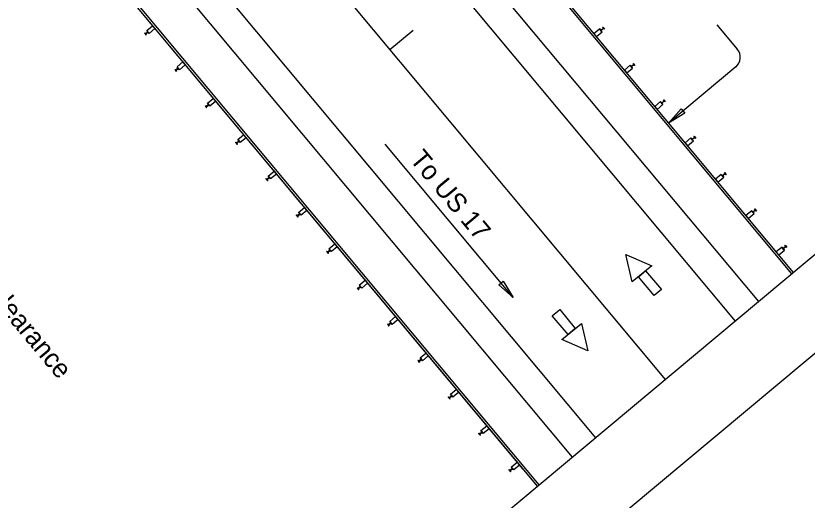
# Model space of a CAD drawing. Extents: x 2042995 to 2043795, y 305365 to 306249.
# Drawn here: x 2043611.9 to 2043716.3, y 305612.5 to 305676.3 of the extents above; entities that cross this region are included whole.
import ezdxf

# ---------------------------------------------------------------- set-up
doc = ezdxf.new("R2010")
doc.units = 0
for name, color, linetype in [('BR_AUTO DIMENSION', 7, 'Continuous'), ('BR_BORDER LINES', 7, 'Continuous'), ('BR_CENTER LINES', 7, 'Continuous'), ('BR_PROPOSED_TRAVELWAY', 7, 'Continuous'), ('BR_STRUCTURAL STEEL', 7, 'Continuous'), ('BR_TABLE LINES', 7, 'Continuous'), ('BR_TEXT', 7, 'Continuous'), ('RD_SHT_IplotShp', 7, 'Continuous')]:
    doc.layers.add(name, color=color, linetype=linetype)

msp = doc.modelspace()

# ---------------------------------------------------------------- linework, layer by layer
at = {"layer": 'BR_AUTO DIMENSION'}
for p, q in [((2043704.39, 305675.16), (2043707.07, 305671.95)), ((2043706.86, 305669.6), (2043698.01, 305662.21)), ((2043677.53, 305639.2), (2043660.64, 305659.42))]:
    msp.add_line(p, q, dxfattribs=at)
for points in [[(2043700.17, 305663.53), (2043698.01, 305662.21), (2043699.69, 305664.1)], [(2043676.21, 305641.35), (2043677.53, 305639.2), (2043675.64, 305640.87)]]:
    msp.add_lwpolyline(points, close=True, dxfattribs=at)
msp.add_arc((2043705.79, 305670.88), 1.67, 309.8684, 39.8684, dxfattribs=at)
at = {"layer": 'BR_BORDER LINES'}
msp.add_line((2043458.12, 305428.42), (2043780.48, 305697.65), dxfattribs=at)
at = {"layer": 'BR_CENTER LINES'}
for p, q in [((2043547.53, 305808.07), (2043697.58, 305628.41)), ((2043661.25, 305671.9), (2043664.32, 305674.46))]:
    msp.add_line(p, q, dxfattribs=at)
at = {"layer": 'BR_PROPOSED_TRAVELWAY'}
for p, q in [((2043592.55, 305788.48), (2043714.46, 305642.51)), ((2043582.48, 305784.94), (2043706.79, 305636.1)), ((2043557.54, 305777.36), (2043688.37, 305620.72)), ((2043564.4, 305753.54), (2043678.77, 305616.61)), ((2043564.46, 305753.47), (2043678.77, 305616.61)), ((2043625.29, 305739.92), (2043709.86, 305638.66)), ((2043608.34, 305710.3), (2043685.3, 305618.15))]:
    msp.add_line(p, q, dxfattribs=at)
at = {"layer": 'BR_STRUCTURAL STEEL'}
for p, q in [((2043611.99, 305764.75), (2043714.24, 305642.32)), ((2043612.21, 305764.94), (2043714.46, 305642.51)), ((2043586.04, 305727.63), (2043680.69, 305614.31)), ((2043586.27, 305727.82), (2043680.92, 305614.49)), ((2043629.27, 305674.37), (2043629.23, 305674.34)), ((2043629.23, 305674.34), (2043629.33, 305674.23)), ((2043629.48, 305674.11), (2043629.27, 305674.37)), ((2043688.97, 305674.55), (2043689, 305674.57)), ((2043689.18, 305674.29), (2043688.97, 305674.55)), ((2043689, 305674.57), (2043689.09, 305674.46)), ((2043689.09, 305674.46), (2043689.41, 305674.73)), ((2043689.44, 305674.7), (2043689.12, 305674.43)), ((2043689.12, 305674.43), (2043689.21, 305674.32)), ((2043689.21, 305674.32), (2043689.18, 305674.29)), ((2043689.32, 305674.84), (2043689.35, 305674.87)), ((2043689.41, 305674.73), (2043689.32, 305674.84)), ((2043689.35, 305674.87), (2043689.57, 305674.61)), ((2043689.53, 305674.58), (2043689.44, 305674.7)), ((2043689.57, 305674.61), (2043689.53, 305674.58)), ((2043628.91, 305674.07), (2043628.88, 305674.05)), ((2043628.88, 305674.05), (2043629.1, 305673.79)), ((2043629.01, 305673.96), (2043628.91, 305674.07)), ((2043629.33, 305674.23), (2043629.01, 305673.96)), ((2043629.03, 305673.93), (2043629.35, 305674.2)), ((2043629.13, 305673.82), (2043629.03, 305673.93)), ((2043629.1, 305673.79), (2043629.13, 305673.82)), ((2043629.35, 305674.2), (2043629.45, 305674.09)), ((2043629.45, 305674.09), (2043629.48, 305674.11)), ((2043693.33, 305670.04), (2043693.36, 305670.07)), ((2043693.36, 305670.07), (2043693.57, 305669.81)), ((2043632.92, 305669.28), (2043632.89, 305669.25)), ((2043632.89, 305669.25), (2043633.1, 305669)), ((2043633.01, 305669.17), (2043632.92, 305669.28)), ((2043633.33, 305669.43), (2043633.01, 305669.17)), ((2043633.04, 305669.13), (2043633.36, 305669.4)), ((2043633.13, 305669.02), (2043633.04, 305669.13)), ((2043633.1, 305669), (2043633.13, 305669.02)), ((2043633.27, 305669.57), (2043633.24, 305669.54)), ((2043633.24, 305669.54), (2043633.33, 305669.43)), ((2043633.49, 305669.32), (2043633.27, 305669.57)), ((2043633.36, 305669.4), (2043633.45, 305669.29)), ((2043633.45, 305669.29), (2043633.49, 305669.32)), ((2043692.97, 305669.75), (2043693.01, 305669.78)), ((2043693.19, 305669.49), (2043692.97, 305669.75)), ((2043693.01, 305669.78), (2043693.1, 305669.66)), ((2043693.1, 305669.66), (2043693.42, 305669.93)), ((2043693.45, 305669.9), (2043693.13, 305669.63)), ((2043693.13, 305669.63), (2043693.22, 305669.52)), ((2043693.22, 305669.52), (2043693.19, 305669.49)), ((2043693.42, 305669.93), (2043693.33, 305670.04)), ((2043693.54, 305669.79), (2043693.45, 305669.9)), ((2043693.57, 305669.81), (2043693.54, 305669.79)), ((2043696.98, 305664.95), (2043697.01, 305664.98)), ((2043697.2, 305664.7), (2043696.98, 305664.95)), ((2043697.01, 305664.98), (2043697.11, 305664.87)), ((2043697.11, 305664.87), (2043697.43, 305665.13)), ((2043697.45, 305665.1), (2043697.13, 305664.84)), ((2043697.33, 305665.25), (2043697.37, 305665.27)), ((2043697.43, 305665.13), (2043697.33, 305665.25)), ((2043697.37, 305665.27), (2043697.58, 305665.02)), ((2043697.55, 305664.99), (2043697.45, 305665.1)), ((2043697.58, 305665.02), (2043697.55, 305664.99)), ((2043636.93, 305664.48), (2043636.89, 305664.45)), ((2043636.89, 305664.45), (2043637.11, 305664.2)), ((2043637.02, 305664.37), (2043636.93, 305664.48)), ((2043637.34, 305664.64), (2043637.02, 305664.37)), ((2043637.05, 305664.34), (2043637.37, 305664.6)), ((2043637.14, 305664.23), (2043637.05, 305664.34)), ((2043637.11, 305664.2), (2043637.14, 305664.23)), ((2043637.28, 305664.77), (2043637.25, 305664.75)), ((2043637.25, 305664.75), (2043637.34, 305664.64)), ((2043637.49, 305664.52), (2043637.28, 305664.77)), ((2043637.37, 305664.6), (2043637.46, 305664.49)), ((2043637.46, 305664.49), (2043637.49, 305664.52)), ((2043697.13, 305664.84), (2043697.23, 305664.72)), ((2043697.23, 305664.72), (2043697.2, 305664.7)), ((2043640.93, 305659.68), (2043640.9, 305659.66)), ((2043640.9, 305659.66), (2043641.11, 305659.4)), ((2043641.03, 305659.57), (2043640.93, 305659.68)), ((2043641.35, 305659.84), (2043641.03, 305659.57)), ((2043641.05, 305659.54), (2043641.37, 305659.81)), ((2043641.28, 305659.98), (2043641.25, 305659.95)), ((2043641.25, 305659.95), (2043641.35, 305659.84)), ((2043641.5, 305659.72), (2043641.28, 305659.98)), ((2043641.37, 305659.81), (2043641.47, 305659.7)), ((2043641.47, 305659.7), (2043641.5, 305659.72)), ((2043700.99, 305660.16), (2043701.02, 305660.18)), ((2043701.2, 305659.9), (2043700.99, 305660.16)), ((2043701.02, 305660.18), (2043701.11, 305660.07)), ((2043701.11, 305660.07), (2043701.43, 305660.34)), ((2043701.46, 305660.31), (2043701.14, 305660.04)), ((2043701.14, 305660.04), (2043701.23, 305659.93)), ((2043701.23, 305659.93), (2043701.2, 305659.9)), ((2043701.34, 305660.45), (2043701.37, 305660.48)), ((2043701.43, 305660.34), (2043701.34, 305660.45)), ((2043701.37, 305660.48), (2043701.59, 305660.22)), ((2043701.55, 305660.19), (2043701.46, 305660.31)), ((2043701.59, 305660.22), (2043701.55, 305660.19)), ((2043641.15, 305659.43), (2043641.05, 305659.54)), ((2043641.11, 305659.4), (2043641.15, 305659.43)), ((2043705.12, 305655.27), (2043705.44, 305655.54)), ((2043705.47, 305655.51), (2043705.15, 305655.24)), ((2043705.35, 305655.65), (2043705.38, 305655.68)), ((2043705.44, 305655.54), (2043705.35, 305655.65)), ((2043705.38, 305655.68), (2043705.59, 305655.42)), ((2043705.56, 305655.4), (2043705.47, 305655.51)), ((2043644.94, 305654.89), (2043644.91, 305654.86)), ((2043644.91, 305654.86), (2043645.12, 305654.6)), ((2043645.03, 305654.77), (2043644.94, 305654.89)), ((2043645.35, 305655.04), (2043645.03, 305654.77)), ((2043645.06, 305654.74), (2043645.38, 305655.01)), ((2043645.15, 305654.63), (2043645.06, 305654.74)), ((2043645.12, 305654.6), (2043645.15, 305654.63)), ((2043645.29, 305655.18), (2043645.26, 305655.15)), ((2043645.26, 305655.15), (2043645.35, 305655.04)), ((2043645.5, 305654.92), (2043645.29, 305655.18)), ((2043645.38, 305655.01), (2043645.47, 305654.9)), ((2043645.47, 305654.9), (2043645.5, 305654.92)), ((2043704.99, 305655.36), (2043705.03, 305655.39)), ((2043705.21, 305655.1), (2043704.99, 305655.36)), ((2043705.03, 305655.39), (2043705.12, 305655.27)), ((2043705.15, 305655.24), (2043705.24, 305655.13)), ((2043705.24, 305655.13), (2043705.21, 305655.1)), ((2043705.59, 305655.42), (2043705.56, 305655.4)), ((2043649.36, 305650.25), (2043649.04, 305649.98)), ((2043649.3, 305650.38), (2043649.27, 305650.36)), ((2043649.27, 305650.36), (2043649.36, 305650.25)), ((2043649.51, 305650.13), (2043649.3, 305650.38)), ((2043709, 305650.56), (2043709.03, 305650.59)), ((2043709.21, 305650.31), (2043709, 305650.56)), ((2043709.03, 305650.59), (2043709.13, 305650.48)), ((2043709.13, 305650.48), (2043709.45, 305650.74)), ((2043709.47, 305650.71), (2043709.15, 305650.44)), ((2043709.15, 305650.44), (2043709.25, 305650.33)), ((2043709.25, 305650.33), (2043709.21, 305650.31)), ((2043709.35, 305650.86), (2043709.38, 305650.88)), ((2043709.45, 305650.74), (2043709.35, 305650.86)), ((2043709.38, 305650.88), (2043709.6, 305650.63)), ((2043709.57, 305650.6), (2043709.47, 305650.71)), ((2043709.6, 305650.63), (2043709.57, 305650.6)), ((2043648.95, 305650.09), (2043648.91, 305650.06)), ((2043648.91, 305650.06), (2043649.13, 305649.81)), ((2043649.04, 305649.98), (2043648.95, 305650.09)), ((2043649.07, 305649.95), (2043649.39, 305650.21)), ((2043649.16, 305649.83), (2043649.07, 305649.95)), ((2043649.13, 305649.81), (2043649.16, 305649.83)), ((2043649.39, 305650.21), (2043649.48, 305650.1)), ((2043649.48, 305650.1), (2043649.51, 305650.13)), ((2043713.36, 305646.06), (2043713.39, 305646.09)), ((2043713.39, 305646.09), (2043713.6, 305645.83)), ((2043652.95, 305645.29), (2043652.92, 305645.27)), ((2043652.92, 305645.27), (2043653.13, 305645.01)), ((2043653.05, 305645.18), (2043652.95, 305645.29)), ((2043653.37, 305645.45), (2043653.05, 305645.18)), ((2043653.07, 305645.15), (2043653.39, 305645.42)), ((2043653.17, 305645.04), (2043653.07, 305645.15)), ((2043653.13, 305645.01), (2043653.17, 305645.04)), ((2043653.3, 305645.59), (2043653.27, 305645.56)), ((2043653.27, 305645.56), (2043653.37, 305645.45)), ((2043653.52, 305645.33), (2043653.3, 305645.59)), ((2043653.39, 305645.42), (2043653.49, 305645.3)), ((2043653.49, 305645.3), (2043653.52, 305645.33)), ((2043713.01, 305645.76), (2043713.04, 305645.79)), ((2043713.22, 305645.51), (2043713.01, 305645.76)), ((2043713.04, 305645.79), (2043713.13, 305645.68)), ((2043713.13, 305645.68), (2043713.45, 305645.95)), ((2043713.48, 305645.91), (2043713.16, 305645.65)), ((2043713.16, 305645.65), (2043713.25, 305645.54)), ((2043713.25, 305645.54), (2043713.22, 305645.51)), ((2043713.45, 305645.95), (2043713.36, 305646.06)), ((2043713.57, 305645.8), (2043713.48, 305645.91)), ((2043713.6, 305645.83), (2043713.57, 305645.8)), ((2043656.96, 305640.5), (2043656.93, 305640.47)), ((2043656.93, 305640.47), (2043657.14, 305640.21)), ((2043657.05, 305640.38), (2043656.96, 305640.5)), ((2043657.37, 305640.65), (2043657.05, 305640.38)), ((2043657.08, 305640.35), (2043657.4, 305640.62)), ((2043657.17, 305640.24), (2043657.08, 305640.35)), ((2043657.14, 305640.21), (2043657.17, 305640.24)), ((2043657.31, 305640.79), (2043657.28, 305640.76)), ((2043657.28, 305640.76), (2043657.37, 305640.65)), ((2043657.52, 305640.53), (2043657.31, 305640.79)), ((2043657.4, 305640.62), (2043657.49, 305640.51)), ((2043657.49, 305640.51), (2043657.52, 305640.53)), ((2043660.96, 305635.7), (2043660.93, 305635.67)), ((2043660.93, 305635.67), (2043661.15, 305635.42)), ((2043661.06, 305635.59), (2043660.96, 305635.7)), ((2043661.38, 305635.85), (2043661.06, 305635.59)), ((2043661.08, 305635.55), (2043661.4, 305635.82)), ((2043661.32, 305635.99), (2043661.28, 305635.97)), ((2043661.28, 305635.97), (2043661.38, 305635.85)), ((2043661.53, 305635.74), (2043661.32, 305635.99)), ((2043661.4, 305635.82), (2043661.5, 305635.71)), ((2043661.5, 305635.71), (2043661.53, 305635.74)), ((2043661.18, 305635.44), (2043661.08, 305635.55)), ((2043661.15, 305635.42), (2043661.18, 305635.44)), ((2043664.97, 305630.9), (2043664.94, 305630.88)), ((2043664.94, 305630.88), (2043665.15, 305630.62)), ((2043665.06, 305630.79), (2043664.97, 305630.9)), ((2043665.38, 305631.06), (2043665.06, 305630.79)), ((2043665.09, 305630.76), (2043665.41, 305631.03)), ((2043665.18, 305630.65), (2043665.09, 305630.76)), ((2043665.15, 305630.62), (2043665.18, 305630.65)), ((2043665.32, 305631.2), (2043665.29, 305631.17)), ((2043665.29, 305631.17), (2043665.38, 305631.06)), ((2043665.54, 305630.94), (2043665.32, 305631.2)), ((2043665.41, 305631.03), (2043665.5, 305630.91)), ((2043665.5, 305630.91), (2043665.54, 305630.94)), ((2043669.39, 305626.26), (2043669.07, 305625.99)), ((2043669.33, 305626.4), (2043669.3, 305626.37)), ((2043669.3, 305626.37), (2043669.39, 305626.26)), ((2043669.54, 305626.14), (2043669.33, 305626.4)), ((2043668.98, 305626.1), (2043668.95, 305626.08)), ((2043668.95, 305626.08), (2043669.16, 305625.82)), ((2043669.07, 305625.99), (2043668.98, 305626.1)), ((2043669.1, 305625.96), (2043669.42, 305626.23)), ((2043669.19, 305625.85), (2043669.1, 305625.96)), ((2043669.16, 305625.82), (2043669.19, 305625.85)), ((2043669.42, 305626.23), (2043669.51, 305626.12)), ((2043669.51, 305626.12), (2043669.54, 305626.14)), ((2043672.98, 305621.31), (2043672.95, 305621.28)), ((2043672.95, 305621.28), (2043673.17, 305621.03)), ((2043673.08, 305621.2), (2043672.98, 305621.31)), ((2043673.4, 305621.46), (2043673.08, 305621.2)), ((2043673.1, 305621.16), (2043673.42, 305621.43)), ((2043673.2, 305621.05), (2043673.1, 305621.16)), ((2043673.17, 305621.03), (2043673.2, 305621.05)), ((2043673.34, 305621.6), (2043673.3, 305621.58)), ((2043673.3, 305621.58), (2043673.4, 305621.46)), ((2043673.55, 305621.35), (2043673.34, 305621.6)), ((2043673.42, 305621.43), (2043673.52, 305621.32)), ((2043673.52, 305621.32), (2043673.55, 305621.35)), ((2043676.99, 305616.51), (2043676.96, 305616.48)), ((2043676.96, 305616.48), (2043677.17, 305616.23)), ((2043677.08, 305616.4), (2043676.99, 305616.51)), ((2043677.4, 305616.67), (2043677.08, 305616.4)), ((2043677.11, 305616.37), (2043677.43, 305616.63)), ((2043677.2, 305616.26), (2043677.11, 305616.37)), ((2043677.17, 305616.23), (2043677.2, 305616.26)), ((2043677.34, 305616.8), (2043677.31, 305616.78)), ((2043677.31, 305616.78), (2043677.4, 305616.67)), ((2043677.56, 305616.55), (2043677.34, 305616.8)), ((2043677.43, 305616.63), (2043677.52, 305616.52)), ((2043677.52, 305616.52), (2043677.56, 305616.55))]:
    msp.add_line(p, q, dxfattribs=at)
for points in [[(2043629.96, 305675.05), (2043630.28, 305674.67), (2043629.51, 305674.03), (2043629.19, 305674.41)], [(2043688.17, 305673.99), (2043688.49, 305673.61), (2043689.26, 305674.25), (2043688.94, 305674.63)], [(2043633.96, 305670.26), (2043634.28, 305669.87), (2043633.51, 305669.23), (2043633.19, 305669.62)], [(2043692.18, 305669.19), (2043692.5, 305668.81), (2043693.27, 305669.45), (2043692.95, 305669.83)], [(2043637.97, 305665.46), (2043638.29, 305665.08), (2043637.52, 305664.43), (2043637.2, 305664.82)], [(2043696.18, 305664.4), (2043696.5, 305664.01), (2043697.27, 305664.65), (2043696.95, 305665.04)], [(2043641.97, 305660.66), (2043642.3, 305660.28), (2043641.53, 305659.64), (2043641.21, 305660.02)], [(2043700.19, 305659.6), (2043700.51, 305659.21), (2043701.28, 305659.86), (2043700.96, 305660.24)], [(2043645.98, 305655.87), (2043646.3, 305655.48), (2043645.53, 305654.84), (2043645.21, 305655.22)], [(2043704.2, 305654.8), (2043704.52, 305654.42), (2043705.29, 305655.06), (2043704.96, 305655.44)], [(2043649.99, 305651.07), (2043650.31, 305650.68), (2043649.54, 305650.04), (2043649.22, 305650.43)], [(2043708.2, 305650), (2043708.52, 305649.62), (2043709.29, 305650.26), (2043708.97, 305650.65)], [(2043653.99, 305646.27), (2043654.31, 305645.89), (2043653.55, 305645.25), (2043653.23, 305645.63)], [(2043712.21, 305645.21), (2043712.53, 305644.82), (2043713.3, 305645.46), (2043712.98, 305645.85)], [(2043658, 305641.47), (2043658.32, 305641.09), (2043657.55, 305640.45), (2043657.23, 305640.83)], [(2043662.01, 305636.68), (2043662.33, 305636.29), (2043661.56, 305635.65), (2043661.24, 305636.04)], [(2043666.01, 305631.88), (2043666.33, 305631.5), (2043665.57, 305630.86), (2043665.25, 305631.24)], [(2043670.02, 305627.08), (2043670.34, 305626.7), (2043669.57, 305626.06), (2043669.25, 305626.44)], [(2043674.03, 305622.29), (2043674.35, 305621.9), (2043673.58, 305621.26), (2043673.26, 305621.65)], [(2043678.03, 305617.49), (2043678.35, 305617.11), (2043677.59, 305616.46), (2043677.26, 305616.85)]]:
    msp.add_lwpolyline(points, close=True, dxfattribs=at)
at = {"layer": 'BR_TABLE LINES'}
for points in [[(2043693.23, 305641.26), (2043692.38, 305644.89), (2043695.79, 305643.4)], [(2043697.06, 305640.26), (2043696.1, 305639.45), (2043694.03, 305641.93), (2043694.99, 305642.73)], [(2043682.68, 305636.79), (2043683.65, 305637.6), (2043685.71, 305635.13), (2043684.75, 305634.32)], [(2043686.51, 305635.79), (2043687.37, 305632.16), (2043683.95, 305633.65)]]:
    msp.add_lwpolyline(points, close=True, dxfattribs=at)
at = {"layer": 'RD_SHT_IplotShp'}
msp.add_lwpolyline([(2043333.03, 306249), (2043794.57, 305696.38), (2043456.86, 305414.33), (2042995.32, 305966.94)], close=True, dxfattribs=at)

# ---------------------------------------------------------------- texts
at = {"layer": 'BR_TEXT'}
for s, p in [('PMVC = Point of Minimum Vertical Clearance', (2043574.31, 305680.12)), ('To US 17', (2043663.78, 305657.36))]:
    msp.add_text(s, height=2.5, rotation=309.8684, dxfattribs=at).set_placement(p)

doc.saveas('drawing.dxf')
